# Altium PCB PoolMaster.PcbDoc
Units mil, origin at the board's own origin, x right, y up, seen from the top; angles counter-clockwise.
Board outline 5590 x 3205 mil, 2 copper layers (Top Layer, Bottom Layer); 45 components, 63 nets, 226 pads, 62 vias.
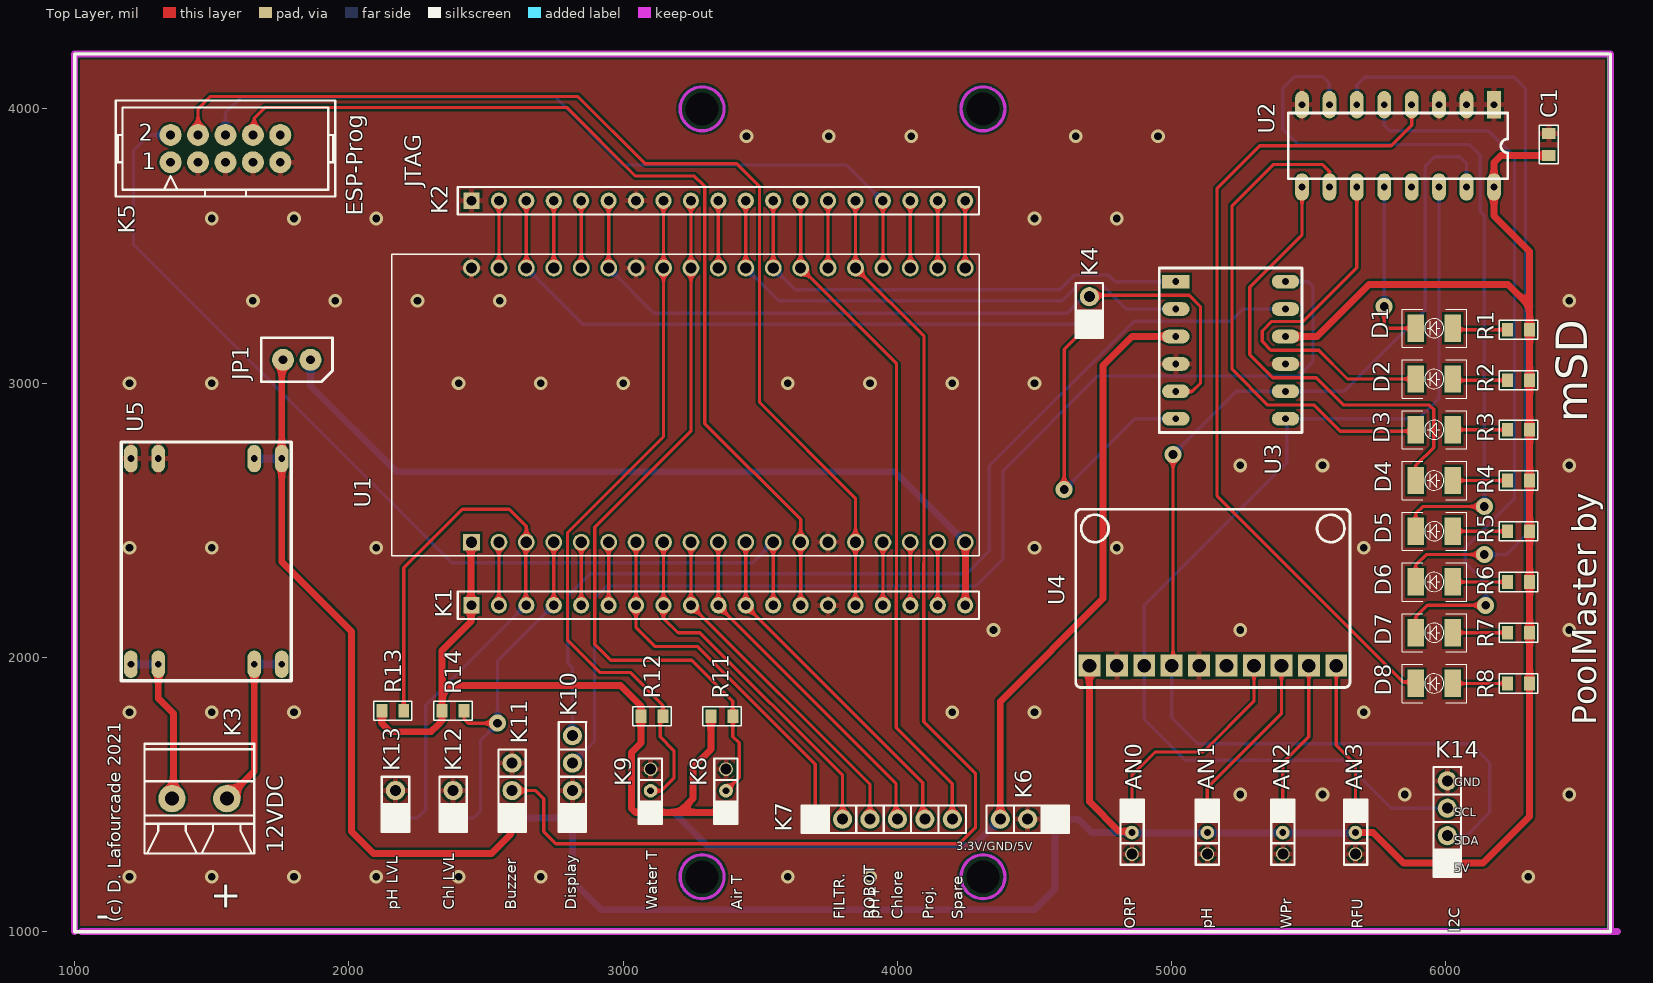
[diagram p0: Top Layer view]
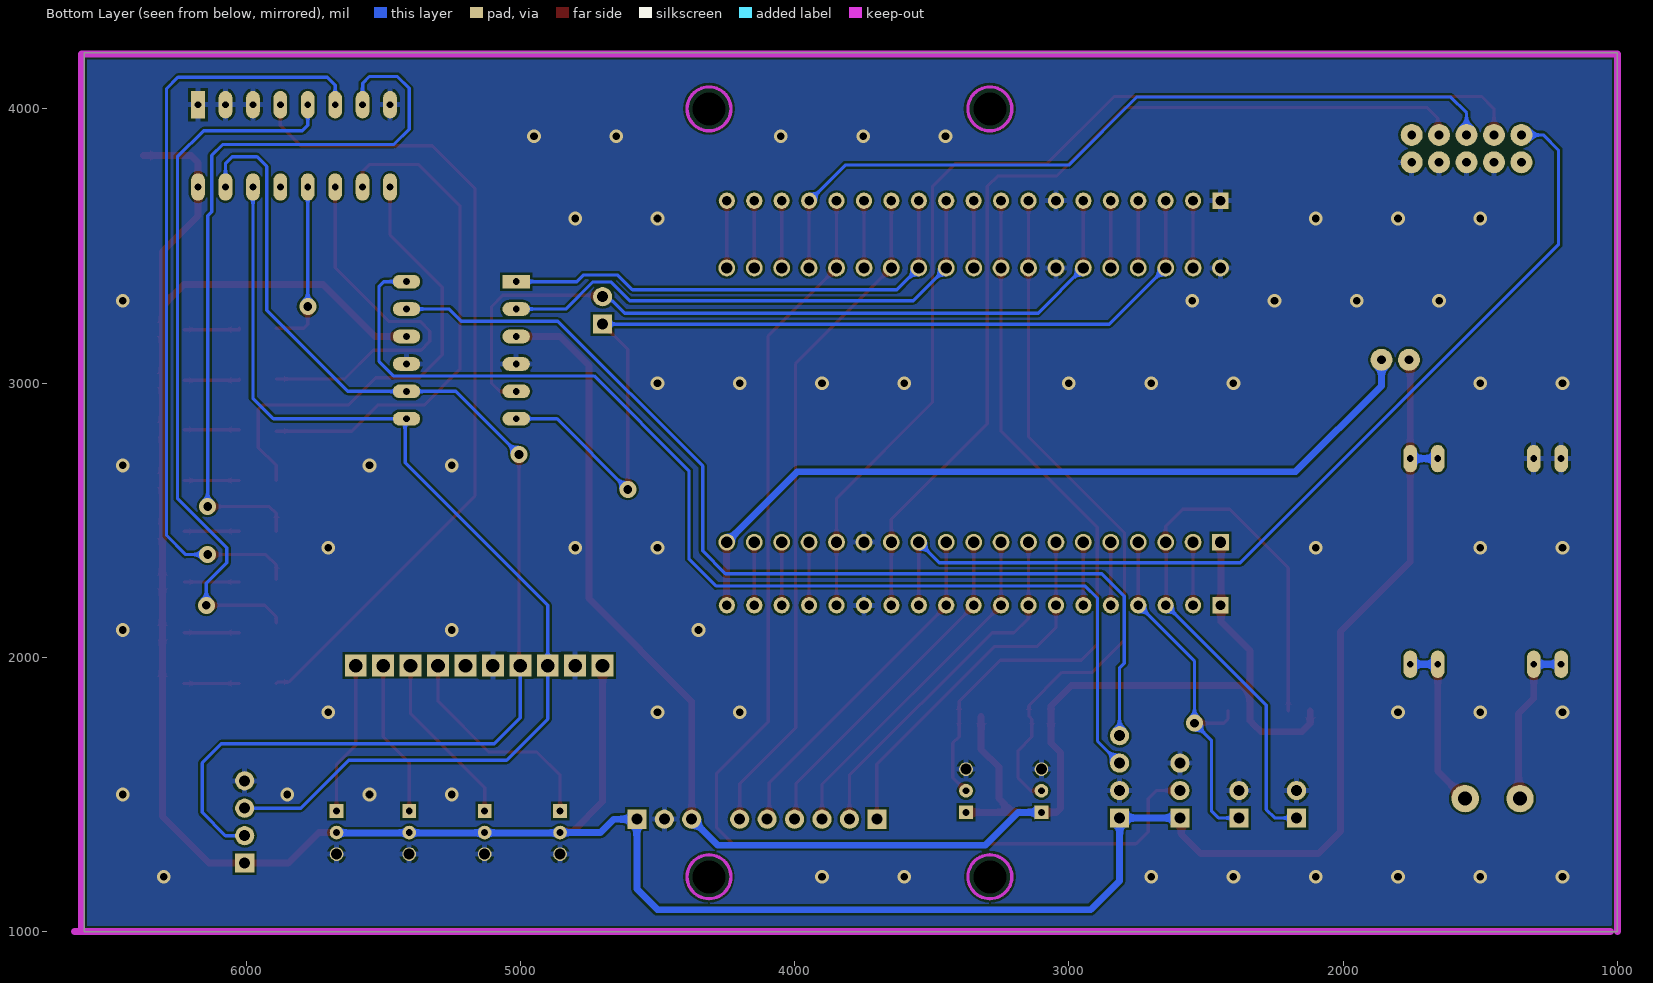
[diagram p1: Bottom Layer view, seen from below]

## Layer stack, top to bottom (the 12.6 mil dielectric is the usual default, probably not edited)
Top Solder: solder mask 0.4, Solder Resist, Dk 3.5
Top Layer: signal copper 1.4
Dielectric 1: dielectric 12.6, FR-4, Dk 4.8
Bottom Layer: signal copper 1.4
Bottom Solder: solder mask 0.4, Solder Resist, Dk 3.5

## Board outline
1000,1000 6590,1000 6590,4205 1000,4205

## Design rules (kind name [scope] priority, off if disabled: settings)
BoardOutlineClearance [All] p1: gap=7.87 ignorepadtopadclearanceinfootprint=FALSE except(15.75: Arc-SplitBarrior Arc-SplitContinuation Track-SplitBarrior Track-SplitContinuation SMDPad-SplitBarrior SMDPad-SplitContinuation THPad-SplitBarrior THPad-SplitContinuation Via-SplitBarrior Via-SplitContinuation Fill-SplitBarrior Fill-SplitContinuation Poly-SplitBarrior Poly-SplitContinuation Region-SplitBarrior Region-SplitContinuation Text-SplitBarrior Text-SplitContinuation)
Clearance "Clearance Bottom Layer" [OnLayer('Bottom Layer')] p1: gap=8 ignorepadtopadclearanceinfootprint=TRUE except(10: Arc-Text Track-Text SMDPad-Text THPad-Text Via-Text Fill-Text Poly-Text Region-Text Text-Text)
Clearance "Clearance Top Layer" [OnLayer('Top Layer')] p2: gap=8 ignorepadtopadclearanceinfootprint=TRUE except(10: Arc-Text Track-Text SMDPad-Text THPad-Text Via-Text Fill-Text Poly-Text Region-Text Text-Text)
Clearance [All] p3: gap=7.87 ignorepadtopadclearanceinfootprint=FALSE except(3.5: Arc-Arc Arc-Track Arc-SMDPad Track-Track Track-SMDPad SMDPad-SMDPad; 5: Arc-Via Track-Via SMDPad-Via THPad-Via Via-Via; 10: Arc-Text Track-Text SMDPad-Text THPad-Text Via-Text Fill-Text Poly-Text Region-Text Text-Text)
HoleSize [All] p1: absolutevalues=TRUE maxlimit=248.03 minlimit=7.87 maxpercent=80.000 minpercent=20.000
MinimumAnnularRing [All] p1: minimumring=3
MinimumSolderMaskSliver [All] p1: minsoldermaskwidth=3.94
PolygonConnect PolygonConnect_1 [All] p1: thpad.connectstyle=Relief thpad.reliefconductorwidth=20 thpad.reliefentries=4 thpad.polygonreliefangle="90 Angle" thpad.airgapwidth=10 smdpad.connectstyle=Relief smdpad.reliefconductorwidth=20 smdpad.reliefentries=4 smdpad.polygonreliefangle="90 Angle" smdpad.airgapwidth=10 via.connectstyle=Direct via.reliefconductorwidth=20 via.reliefentries=4 via.polygonreliefangle="90 Angle" via.airgapwidth=10
RoutingCorners [All] p1: cornerstyle=Round minsetback=100 maxsetback=100
RoutingVias [All] p1: holewidth=19.68 width=39.37 viastyle="Through Hole" minholewidth=7.87 minwidth=17.72 maxholewidth=39.37 maxwidth=78.74
SilkToSilkClearance [All] p1: silktosilkclearance=3.94
SilkToSolderMaskClearance [IsPad] p1: minsilkscreentomaskgap=3.94 clearancetoexposedcopper=TRUE
SolderMaskExpansion [All] p1: expansion=4 istentingtop=FALSE
Width [All] p1: maxlimit=100 minlimit=3.5 preferedwidth=15
25 further rules are at their usual default settings.

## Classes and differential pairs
net class Power: 3V3 5V GND NetJP1_1 NetK3_1 NetK3_2

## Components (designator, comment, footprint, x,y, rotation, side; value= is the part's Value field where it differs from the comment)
AN0 "HEADER 3" JST-1X3 4855,1440 r0 top
AN1 "HEADER 3" JST-1X3 5130,1440 r0 top
AN2 "HEADER 3" JST-1X3 5405,1440 r0 top
AN3 "HEADER 3" JST-1X3 5670,1440 r0 top
C1 "100n" 0805C-GENERIC 6375,3840 r90 top
D1 "Red" TOPLED-RED 6025,3200 r180 top
D2 "Red" TOPLED-RED 6025,3015 r180 top
D3 "Red" TOPLED-RED 6025,2830 r180 top
D4 "Red" TOPLED-RED 6025,2645 r180 top
D5 "Green" TOPLED-GREEN 6025,2460 r180 top
D6 "Green" TOPLED-GREEN 6025,2275 r180 top
D7 "Yellow" TOPLED-YELLOW 6025,2090 r180 top
D8 "Blue" TOPLED-BLUE 6025,1905 r180 top
JP1 "U/L" 2_PADS 1860,3085 r180 top
K1 "Header 19" HDR1X19 2447,2190 r0 top
K2 "Header 19" HDR1X19 2447,3665 r0 top
K3 "12VDC" MKDS15_2RMI 1555,1485 r180 top
K4 "I2C" HEADER-1X2 4700,3215 r180 top
K5 "ESP-Prog" HE10_10 1350,3805 r0 top
K6 "HEADER 3" HEADER-1X3 4575,1410 r270 top
K7 "HEADER 6" HEADER-1X6 3700,1410 r90 top
K8 "Air T" JST-1X3 3375,1435 r180 top
K9 "Water T" JST-1X3 3100,1435 r180 top
K10 "Display" HEADER-1X4 2815,1414.48 r180 top
K11 "Buzzer" HEADER-1X3 2595,1414.48 r180 top
K12 "Chl LVL" HEADER-1X2 2380,1414.48 r180 top
K13 "pH LVL" HEADER-1X2 2170,1414.48 r180 top
K14 "I2C-5V" HEADER-1X4 6005,1250 r180 top
R1 "3k3" 0805R-3K3 6295,3195 r180 top
R2 "3k3" 0805R-3K3 6295,3010 r180 top
R3 "3k3" 0805R-3K3 6295,2830 r180 top
R4 "3k3" 0805R-3K3 6295,2645 r180 top
R5 "3k3" 0805R-3K3 6295,2460 r180 top
R6 "3k3" 0805R-3K3 6295,2275 r180 top
R7 "3k3" 0805R-3K3 6295,2090 r180 top
R8 "3k3" 0805R-3K3 6295,1905 r180 top
R11 "10k" 0805R-10K 3320,1785 r0 top
R12 "10k" 0805R-10K 3065,1785 r0 top
R13 "10k" 0805R-10K 2120,1805 r0 top
R14 "10k" 0805R-10K 2340,1805 r0 top
U1 "ESP32-DEVKITC-32E" MODULE_ESP32-DEVKITC-32D 3225,2920 r90 top
U2 "PCF8574AN" DIP16 6175,4015 r270 top
U3 "SHIFTER 4CH" "SHIFTER 4CH" 5015,3370 r0 top
U4 "ADS1115" "ADS1115 Module" 5150,1970 r0 top
U5 "MP1584EN" MP1884EN 1205,1975 r90 top

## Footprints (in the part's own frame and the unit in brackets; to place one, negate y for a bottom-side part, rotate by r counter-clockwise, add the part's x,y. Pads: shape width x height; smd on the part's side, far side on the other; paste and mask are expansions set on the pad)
2_PADS [mil]
  round 80 hole 32: 1(0,0) 2(100,0)
  silkscreen extent -80,-80 180,80, body extent -50,-49 150,49, height 336
0805C-GENERIC [mil] "CAPACITOR 0805"
  rect 40x50 smd: 1(-10,0) 2(70,0)
  silkscreen extent -40,-35 100,35, body extent -11,-25 70,25, height 26
0805R-3K3 [mil] "RESISTOR 0805"
  rect 40x50 smd: 1(-10,0) 2(70,0)
  silkscreen extent -40,-35 100,35, body extent -11,-25 70,25, height 27
0805R-10K [mil] "RESISTOR 0805"
  rect 40x50 smd: 1(0,0) 2(80,0)
  silkscreen extent -30,-35 110,35, body extent -1,-25 80,25, height 27
"ADS1115 Module" [mil] "4 channels I2C ADC"
  rect 80x80 hole 50: 1(-450,0) 2(-350,0) 3(-250,0) 4(-150,0) 5(-50,0) 6(50,0) 7(150,0) 8(250,0) 9(350,0) 10(450,0)
  silkscreen extent -500,-80 500,570, body extent -550,-79 550,601, height 228
DIP16 [mil]
  rect 100x50 hole 25: 1(0,0)
  oval 100x50 hole 25: 2(0,-100) 3(0,-200) 4(0,-300) 5(0,-400) 6(0,-500) 7(0,-600) 8(0,-700) 9(300,-700) 10(300,-600) 11(300,-500) 12(300,-400) 13(300,-300) 14(300,-200) 15(300,-100) 16(300,0)
  silkscreen extent 30,-750 270,50, body extent -56,-751 357,52, height 317
HDR1X19 [mm] "Connector; Header; 19 Position"
  rect 1.5x1.5 hole 0.9: 1(0,0)
  round 1.5 hole 0.9: 2(2.54,0) 3(5.08,0) 4(7.62,0) 5(10.16,0) 6(12.7,0) 7(15.24,0) 8(17.78,0) 9(20.32,0) 10(22.86,0) 11(25.4,0) 12(27.94,0) 13(30.48,0) 14(33.02,0) 15(35.56,0) 16(38.1,0) 17(40.64,0) 18(43.18,0) 19(45.72,0)
  silkscreen extent -1.27,-1.27 46.99,1.27, body extent -1.4,-1.4 47.12,1.1, height 8.5
HE10_10 [mil]
  round 80 hole 32: 1(0,0) 2(0,100) 3(100,0) 4(100,100) 5(200,0) 6(200,100) 7(300,0) 8(300,100) 9(400,0) 10(400,100)
  silkscreen extent -200,-125 600,225, body extent -200,-135 600,225, height 354
HEADER-1X2 [mil]
  rect 70x70 hole 40: 1(0,0)
  round 70 hole 40: 2(0,-100)
  silkscreen extent -50,-150 50,50, body extent -50,-150 50,50, height 470
HEADER-1X3 [mil]
  rect 70x70 hole 40: 1(0,0)
  round 70 hole 40: 2(0,-100) 3(0,-200)
  silkscreen extent -50,-250 50,50, body extent -50,-250 50,50, height 470
HEADER-1X4 [mil]
  rect 70x70 hole 40: 1(0,0)
  round 70 hole 40: 2(0,-100) 3(0,-200) 4(0,-300)
  silkscreen extent -51,-350 50,50, body extent -50,-350 50,50, height 470
HEADER-1X6 [mil]
  rect 70x70 hole 40: 1(0,0)
  round 70 hole 40: 2(0,-100) 3(0,-200) 4(0,-300) 5(0,-400) 6(0,-500)
  silkscreen extent -50,-550 50,50, body extent -50,-550 50,50, height 470
JST-1X3 [mm] "JST 3 M"
  rect 1.27x1.27 hole 0.635: 1(0,0)
  round 1.27 hole 0.635: 2(0,-2)
  round 1.27 hole 1.016: 3(0,-4)
  silkscreen extent -1.07,-4.98 1.12,1.07, body extent -2.89,-6.01 1.61,1.89, height 6
MKDS15_2RMI [mm]
  round 2.54 hole 1.3: 1(0,0) 2(5.08,0)
  silkscreen extent -2.54,-5.08 7.62,5.08, body extent -2.87,-4.11 7.7,4.89, height 11.54
MODULE_ESP32-DEVKITC-32D [mm]
  rect 1.56x1.56 hole 1.04: 1(-12.7,19.76)
  round 1.56 hole 1.04: 2(-12.7,17.22) 3(-12.7,14.68) 4(-12.7,12.14) 5(-12.7,9.6) 6(-12.7,7.06) 7(-12.7,4.52) 8(-12.7,1.98) 9(-12.7,-0.56) 10(-12.7,-3.1) 11(-12.7,-5.64) 12(-12.7,-8.18) 13(-12.7,-10.72) 14(-12.7,-13.26) 15(-12.7,-15.8) 16(-12.7,-18.34) 17(-12.7,-20.88) 18(-12.7,-23.42) 19(-12.7,-25.96) 20(12.7,19.76) 21(12.7,17.22) 22(12.7,14.68) 23(12.7,12.14) 24(12.7,9.6) 25(12.7,7.06) 26(12.7,4.52) 27(12.7,1.98) 28(12.7,-0.56) 29(12.7,-3.1) 30(12.7,-5.64) 31(12.7,-8.18) 32(12.7,-10.72) 33(12.7,-13.26) 34(12.7,-15.8) 35(12.7,-18.34) 36(12.7,-20.88) 37(12.7,-23.42) 38(12.7,-25.96)
  silkscreen extent -13.95,-27.25 13.95,27.15, body extent -13.84,-31.3 14.1,24.28, height 7.14
MP1884EN [mil] "BoB MP1584EN DC-DC"
  oval 100x50 hole 25: 1(0,0) 2(0,-100) 3(0,-450) 4(0,-550) 5(750,-550) 6(750,-450) 7(750,-100) 8(750,0)
  silkscreen extent -60,-585 810,35, body extent -59,-610 807,60, height 268
"SHIFTER 4CH" [mil] "4 channels signal shifter"
  rect 100x50 hole 25: 1(0,0)
  oval 100x50 hole 25: 2(0,-100) 3(0,-200) 4(0,-300) 5(0,-400) 6(0,-500) 7(400,-500) 8(400,-400) 9(400,-300) 10(400,-200) 11(400,-100) 12(400,0)
  silkscreen extent -60,-550 460,50, body extent -100,-657 500,149, height 217
TOPLED-BLUE [mil]
  rect 60x100 smd: A(0,0) K(135,0)
  silkscreen extent -50,-70 185,70, body extent -20,-60 154,60, height 75
TOPLED-GREEN [mil]
  rect 60x100 smd: A(0,0) K(135,0)
  silkscreen extent -50,-70 185,70, body extent -20,-60 154,60, height 75
TOPLED-RED [mil]
  rect 60x100 smd: A(0,0) K(135,0)
  silkscreen extent -50,-70 185,70, body extent -20,-60 154,60, height 75
TOPLED-YELLOW [mil]
  rect 60x100 smd: A(0,0) K(135,0)
  silkscreen extent -50,-70 185,70, body extent -20,-60 154,60, height 75

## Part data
C1: library part CAP, "Capacitor"
D1 D2 D3 D4 D5 D6 D7 D8: library part LED
JP1: library part JUMPER, "Jumper"
K1 K2: "Header, 19-Pin"
K3 K4 K12 K13: library part "Header 2", "Header, 2-Pin"
K5: library part "Header 5X2", "Header, 5-Pin, Dual row"
K8 K9 K11: library part "Header 3", "Header, 3-Pin"
K10 K14: library part "Header 4", "Header, 4-Pin"
R1 R2 R3 R4 R5 R6 R7 R8 R11 R12 R13 R14: library part RES2, "Resistor"
U1: library part ESP32-DEVKITC-32D, "- Transceiver; 802.11 b/g/n _Wi-Fi, WiFi, WLAN_, BluetoothÂ® Smart Ready 4.x Dual Mode For Use With ESP-WROOM-32", Package=None
U2: "Remote 8-Bit I/O Expander for I2C-Bus, 2.5 to 6 V, -40 to 85 degC, 16-pin PDIP (N), Pb-Free (RoHS)", Manufacturer="Texas Instruments", Max Frequency(kHz)=100, Supplier Part Number 1=296-13106-5-ND, Voltage Nodes(V)="5, 3.3"

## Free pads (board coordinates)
  round 100 hole 120: 10(3288,4000) 11(4312,4000) 12(4312,1200)
  round 100 hole 120 unplated: 13(3288,1200)

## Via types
v1: diameter 50, hole 28, Top Layer to Bottom Layer, 55 vias
v2: diameter 62, hole 32, Top Layer to Bottom Layer, 7 vias

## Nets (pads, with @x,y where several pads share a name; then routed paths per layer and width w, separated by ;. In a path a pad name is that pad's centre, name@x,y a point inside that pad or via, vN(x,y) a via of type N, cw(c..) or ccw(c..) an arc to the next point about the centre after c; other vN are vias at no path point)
3V3: K1.1 K6.3 K8.1 K9.1 R11.1 R12.1 R13.1 R14.1 U1.1 U3.3 | length 6377.3
  Top Layer w25: R13.1 2120,1759 2150,1729 2300,1729 2325.25,1754.25 2340,1769 2340,1769.5 R14.1 2340,1837 2340,1867 ; U1.1 2445,2417.95 2445,2190 2445,2130 2340,2025 2340,1867 ; R11.1 3320,1665 3255,1600 3255,1485 3205,1435 ; K8.1 3205,1435 ; K6.3 4375,1840 4750,2215 4750,2980 4750,3064 4856,3170 U3.3 ; 2340,1867 2370,1897 2950,1897 2991,1897 3065,1823 R12.1 3065,1688 3030,1653 3030,1449.64 3044.64,1435 3205,1435
  Bottom Layer w25: K9.1 3185,1435 3305,1315 4280,1315 K6.3
5V: AN0.2 AN1.2 AN2.2 AN3.2 C1.1 JP1.2 K6.1 K10.1 K11.1 K14.1 R1.1 R2.1 R3.1 R4.1 R5.1 R6.1 R7.1 R8.1 U2.16 U3.10 U4.1 U5.5 U5.6 | length 11395.1
  Top Layer w25: JP1.2 1755,3080 U5.5 1755,2350 2010,2095 2010,1365 2090,1285 2520,1285 2590,1355 2590,1409.48 K11.1 ; U4.1@4700,1974.55 4700,1473.74 4807.7,1366.04 4850.22,1366.04 AN0.2 ; U3.10 5530,3170 5720,3360 6226,3360 6305,3281 ; AN3.2@5671.26,1360 AN3.2 5733.74,1361.26 5845,1250 K14.1 6135,1250 6305,1420 R8.1 R7.1 R5.1 R4.1 R2.1 R1.1 6305,3281 ; C1.1 6200,3830 6175,3805 6175,3610 6305,3480 6305,3281
  Bottom Layer w25: U5.6 U5.5 ; K11.1 K10.1 2815,1185 2920,1080 4500,1080 4575,1155 K6.1 4658.74,1410 4707.48,1361.26 AN0.2 4856.26,1360 5128.74,1360 AN1.2 5131.26,1360 5403.74,1360 AN2.2 5406.26,1360 5668.74,1360 AN3.2
GND: AN0.3 AN1.3 AN2.3 AN3.3 C1.2 K1.14 K2.1 K2.7 K5.3 K5.5 K5.7 K5.9 K6.2 K8.3 K9.3 K10.2 K11.3 K12.2 K13.2 K14.4 U1.14 U1.20 U1.26 U2.1 U2.2 U2.3 U2.8 U3.4 U3.9 U4.2 U4.5 U5.7 U5.8
  other v1: 1200,1200 1500,1200 1800,1200 2100,1200 2400,1200 2700,1200 3600,1200 3900,1200 6300,1200 5250,1500 5550,1500 5850,1500 6450,1500 1200,1800 1500,1800 1800,1800 4200,1800 4500,1800 5700,1800 4350,2100 5250,2100 6450,2100 1200,2400 1500,2400 2100,2400 4500,2400 4800,2400 5700,2400 5250,2700 5550,2700 6450,2700 1200,3000 1500,3000 2400,3000 2700,3000 3000,3000 3600,3000 3900,3000 4200,3000 4500,3000 1650,3300 1950,3300 2250,3300 2550,3300 6450,3300 1500,3600 1800,3600 2100,3600 4500,3600 4800,3600 3450,3900 3750,3900 4050,3900 4650,3900 4950,3900
NetAN0_1: AN0.1 U4.7 | length 816.8
  Top Layer w12: AN0.1 4855,1570 4940,1655 5115,1655 5300,1840 U4.7
NetAN1_1: AN1.1 U4.8 | length 641.8
  Top Layer w12: AN1.1 5130,1525 5400,1795 U4.8
NetAN2_1: AN2.1 U4.9 | length 569.4
  Top Layer w12: AN2.1 5405,1615 5500,1710 U4.9
NetAN3_1: AN3.1 U4.10 | length 559
  Top Layer w12: U4.10 5600,1680 5670,1610 AN3.1
NetD1_1: D1.A R1.2 | length 205
  Top Layer w12: D1.A 6025,3195 R1.2
NetD1_2: D1.K U2.12 | length 621.2
  Top Layer w12: v2(5775,3279) 5775,3215 5790.03,3199.97 5828,3199.97 ; 5828.03,3200 D1.K
  Bottom Layer w12: v2(5775,3279) U2.12
NetD2_1: D2.A R2.2 | length 205
  Top Layer w12: D2.A 6025,3010 R2.2
NetD2_2: D2.K U2.11 | length 1390
  Top Layer w12: U2.11 5675,3420 5480,3225 5365,3225 5330,3190 5330,3152.03 5362.03,3120 5536,3120 5641,3015 D2.K
NetD3_1: D3.A R3.2 | length 200
  Top Layer w12: D3.A R3.2
NetD3_2: D3.K U2.10 | length 1844.7
  Top Layer w12: U2.10 5575,3772 5550,3797 5370,3797 5220,3647 5220,3050 5350,2920 5520,2920 5615,2825 D3.K@5890,2825
NetD4_1: D4.A R4.2 | length 200
  Top Layer w12: D4.A R4.2
NetD4_2: D4.K U2.9 | length 1728.7
  Top Layer w12: U2.9 5475,3540 5285,3350 5285,3104 5369,3020 5527,3020 5627,2920 5939.46,2920 5955,2904.46 5955,2765 5890,2700 D4.K
NetD5_1: D5.A R5.2 | length 200
  Top Layer w12: D5.A R5.2
NetD5_2: D5.K U2.7 | length 2796.5
  Top Layer w12: D5.K 5890,2525 5915,2550 v2(6140,2550)
  Bottom Layer w12: U2.7 5575,4093 5550,4118 5448,4118 5405,4075 5405,3926 5461,3870 6085,3870 6125,3830 6125,3625 6140,3610 v2(6140,2550)
NetD6_1: D6.A R6.2 | length 200
  Top Layer w12: D6.A R6.2
NetD6_2: D6.K U2.6 | length 2840.3
  Top Layer w12: D6.K@5890,2285 5890,2337 5928,2375 v2(6140,2375)
  Bottom Layer w12: U2.6 5675,4086 5704,4115 6248.33,4115 6290,4073.33 6290,2445 6220,2375 v2(6140,2375)
NetD7_1: D7.A R7.2 | length 200.5
  Top Layer w12: D7.A R7.2@6225.47,2090
NetD7_2: D7.K U2.5 | length 2633.4
  Top Layer w12: D7.K@5890,2125 5890,2147.5 5932.5,2190 v2(6145,2190)
  Bottom Layer w12: U2.5 5775,3940 5795,3920 6155,3920 6250,3825 6250,2580 6070,2400 6070,2345 6145,2270 v2(6145,2190)
NetD8_1: D8.A R8.2 | length 203.3
  Top Layer w12: D8.A R8.2@6228.35,1905
NetD8_2: D8.K U2.4 | length 3008.4
  Top Layer w12: U2.4 5875,3940 5800,3865 5321,3865 5165,3709 5165,2590 5845,1910 5885,1910 D8.K
NetJP1_1: JP1.1 K1.19 U1.19 | length 2951.5
  Top Layer w25: K1.19@4245,2190 4248,2190 4248,2419.05 U1.19
  Bottom Layer w25: JP1.1 1860,2990 2173,2677 3990.05,2677 U1.19
NetK1_2: K1.2 U1.2 | length 230.8
  Top Layer w12: K1.2@2545,2190 2547.05,2192.05 U1.2
NetK1_3: K1.3 K13.1 R13.2 U1.3 | length 2390
  Top Layer w12: R13.2 2200,2326 2414,2540 2585,2540 2647.05,2477.95 U1.3 2645,2417.95 2645,2400 K1.3@2645,2190
  Bottom Layer w12: K13.1 2249.48,1414.48 2280,1445 2280,1825 K1.3@2645,2190
NetK1_4: K1.4 K12.1 R14.2 U1.4 | length 1359.4
  Top Layer w12: R14.2 2420,1775 2435,1760 v2(2542,1760) ; K1.4@2745,2190 2747.05,2192.05 U1.4
  Bottom Layer w12: K12.1 2454.48,1414.48 2480,1440 2480,1698 v2(2542,1760) 2542,1987 K1.4@2745,2190
NetK1_5: K1.5 U1.5 | length 230.8
  Top Layer w12: K1.5@2845,2190 2847.05,2192.05 U1.5
NetK1_6: K1.6 U1.6 | length 230.8
  Top Layer w12: K1.6@2945,2190 2947.05,2192.05 U1.6
NetK1_7: K1.7 K7.1 U1.7 | length 1371.3
  Top Layer w12: U1.7 K1.7 3047,2108 3115,2040 3270,2040 3700,1610 K7.1
NetK1_8: K1.8 K7.2 U1.8 | length 1327.4
  Top Layer w12: U1.8 K1.8 3147,2143 3200,2090 3280,2090 3800,1570 K7.2
NetK1_9: K1.9 K7.3 U1.9 | length 1280.5
  Top Layer w12: U1.9 K1.9 3900,1537 K7.3
NetK1_10: K1.10 K7.4 U1.10 | length 1282.2
  Top Layer w12: U1.10 3347.05,2192.05 3345,2190 3475,2060 3994.52,1540.48 3994.52,1415.48 K7.4
NetK1_11: K1.11 K7.5 U1.11 | length 1282.2
  Top Layer w12: U1.11 3447.05,2192.05 3445,2190 4092.02,1542.98 4092.02,1417.98 K7.5
NetK1_12: K1.12 K5.2 U1.12 | length 3577.2
  Top Layer w12: K1.12@3545,2190 3547.05,2192.05 U1.12
  Bottom Layer w12: K5.2 1270,3905 1215,3850 1215,3505 2375,2345 3472.05,2345 U1.12
NetK1_13: K1.13 K5.8 U1.13 | length 3513.5
  Top Layer w12: K5.8 1655,3910 1655,3965 1695,4005 1715,4005 2795,4005 3045,3755 3260,3755 3294.03,3720.97 3297.54,3717.46 3297.54,3424.52 3297.34,3424.31 3297.34,3415.69 3297.54,3415.48 3297.54,2852.46 3647.05,2502.95 U1.13 3647.05,2192.05 K1.13@3645,2190
NetK1_15: K1.15 K5.4 U1.15 | length 3969.9
  Top Layer w12: K5.4 1450,4000 1495,4045 2835,4045 3080,3800 3415,3800 3496.88,3718.12 3496.88,2931.12 3847.05,2580.95 U1.15 3847.05,2192.05 K1.15@3845,2190
NetK1_16: K1.16 U1.16 | length 230.8
  Top Layer w12: K1.16@3945,2190 3947.05,2192.05 U1.16
NetK1_17: K1.17 U1.17 | length 230.8
  Top Layer w12: K1.17@4045,2190 4047.05,2192.05 U1.17
NetK1_18: K1.18 U1.18 | length 230.8
  Top Layer w12: K1.18@4145,2190 4147.05,2192.05 U1.18
NetK2_2: K2.2 U1.21 | length 245.8
  Top Layer w12: K2.2@2545,3665 2547.05,3662.95 U1.21
NetK2_3: K2.3 K4.1 U1.22 U3.6 | length 3538.7
  Top Layer w12: K2.3@2645,3665 2647.05,3662.95 U1.22 ; v2(4608,2612) 4608,3123 K4.1
  Bottom Layer w12: U1.22 2852.05,3215 K4.1 ; v2(4608,2612) 4866,2870 U3.6
NetK2_4: K2.4 U1.23 | length 245.8
  Top Layer w12: K2.4@2745,3665 2747.05,3662.95 U1.23
NetK2_5: K2.5 U1.24 | length 245.8
  Top Layer w12: K2.5@2845,3665 2847.05,3662.95 U1.24
NetK2_6: K2.6 K4.2 U1.25 U3.5 | length 2897.5
  Top Layer w12: K2.6@2945,3665 2947.05,3662.95 U1.25 ; K4.2 4705,3320 4787.97,3320 5064,3320 5105,3279 5105,3000 5075,2970 U3.5
  Bottom Layer w12: U1.25 3112.05,3255 4620,3255 4664.52,3299.52 4668.83,3299.52 4684.31,3315 K4.2
NetK2_8: K2.8 K9.2 R12.2 U1.27 | length 2588.2
  Top Layer w12: K9.2 3138.74,1513.74 3185,1560 3185,1660 3135,1710 3135,1775 R12.2 3145,1825 3025,1945 2915,1945 2797.34,2062.66 2797.34,2455.34 3147.05,2805.05 U1.27 3147.05,3662.95 K2.8@3145,3665
NetK2_9: K2.9 K8.2 R11.2 U1.28 | length 2707.9
  Top Layer w12: K2.9@3245,3665 3247.05,3662.95 U1.28 3247.05,2825 2896.76,2474.71 2896.76,2048.24 2955,1990 3250,1990 3400,1840 R11.2 3400,1711 3423,1688 3423,1561.74 K8.2
NetK2_10: K2.10 U1.29 | length 245.8
  Top Layer w12: K2.10@3345,3665 3347.05,3662.95 U1.29
NetK2_11: K2.11 U1.30 U3.2 | length 1933.1
  Top Layer w12: K2.11@3445,3665 3447.05,3662.95 U1.30
  Bottom Layer w12: U1.30 3567.05,3300 4601,3300 4670,3369 4735,3369 4834,3270 U3.2
NetK2_12: K2.12 U1.31 U3.1 | length 1779.2
  Top Layer w12: K2.12@3545,3665 3547.05,3662.95 U1.31
  Bottom Layer w12: U1.31 3627.05,3340 4591,3340 4645,3394 4770,3394 4794,3370 U3.1
NetK2_13: K2.13 K7.6 U1.32 | length 2485.7
  Top Layer w12: K2.13@3645,3665 3647.05,3662.95 U1.32 3997,3070.05 3997,2254 3996,2253 3996,1744 4200,1540 K7.6
NetK2_14: K2.14 U1.33 | length 245.8
  Top Layer w12: K2.14@3745,3665 3747.05,3662.95 U1.33
NetK2_15: K2.15 K11.2 U1.34 | length 4333.8
  Top Layer w12: K11.2 2680.52,1514.48 2710,1485 2710,1365 2755,1320 4225,1320 4285,1380 4285,1576 4096,1765 4096,2345 4097,2346 4097,3170.05 U1.34 3847.05,3662.95 K2.15@3845,3665
NetK2_16: K2.16 K5.6 U1.35 | length 2901.9
  Top Layer w12: K2.16@3945,3665 3947.05,3662.95 U1.35
  Bottom Layer w12: K5.6 1550,3985 1608.5,4043.5 2751.5,4043.5 3000,3795 3815,3795 K2.16@3945,3665
NetK2_17: K2.17 U1.36 | length 245.8
  Top Layer w12: K2.17@4045,3665 4047.05,3662.95 U1.36
NetK2_18: K2.18 U1.37 | length 245.8
  Top Layer w12: K2.18@4145,3665 4147.05,3662.95 U1.37
NetK2_19: K2.19 U1.38 | length 245.8
  Top Layer w12: K2.19@4245,3665 4247.05,3662.95 U1.38
NetK3_1: K3.1 U5.3 U5.4 | length 631.4
  Top Layer w25: K3.1 1655,1585 U5.3
  Bottom Layer w25: U5.3 U5.4
NetK3_2: K3.2 U5.1 U5.2 | length 614.9
  Top Layer w25: U5.2 1305,1850 1360,1795 1360,1490 K3.2
  Bottom Layer w25: U5.1 U5.2
NetK10_3: K10.3 U3.12 | length 4180.3
  Bottom Layer w12: K10.3 2895.53,1695.01 2895.53,2215.53 2940,2260 4285,2260 4385,2360 4385,2680 4731,3026 5462.5,3026 5515,3078.5 5515,3352.97 5497.97,3370 U3.12
NetK10_4: K10.4 U3.11 | length 3747.4
  Bottom Layer w12: K10.4 2815,1961.87 2798.47,1978.4 2798.47,2223.47 2880,2305 4252,2305 4335,2388 4335,2698 4863,3226 5215,3226 5259,3270 U3.11
NetK14_2: K14.2 U2.15 U3.8 U4.4 | length 4482.9
  Top Layer w12: U4.4 5005,1975 v2(5005,2740)
  Bottom Layer w12: U4.4 5000,1780 5095,1685 6090,1685 6160,1615 6160,1435 6075,1350 K14.2 ; v2(5005,2740) 5235,2970 U3.8 5630,2970 5925,3265 5925,3790 5960,3825 6050,3825 6075,3800 U2.15
NetK14_3: K14.3 U2.14 U3.7 U4.3 | length 3913.1
  Bottom Layer w12: U2.14 5975,2945 5900,2870 U3.7 5420,2865 5420,2710 4900,2190 U4.3 4900,1775 5050,1625 5625,1625 5800,1450 K14.3
pads on no net: K5.1 K5.10 U2.13 U4.6

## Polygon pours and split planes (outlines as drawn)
GND on Top Layer "GND_L01_P000" (solid, pour order 0): 6600,4200 6600,1000 1000,1000 1000,4200
GND on Bottom Layer "GND_L02_P001" (solid, pour order 1): 1007.5,4200 6590,4200 6600,4210 6605,4205 6605,1000 1010,1000 1000,1010 1000,4205

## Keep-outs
Keep-Out Layer:
  circle w12: c4312,1200 r80
  circle w12: c3288,1200 r80
  circle w12: c4312,4000 r80
  circle w12: c3288,4000 r80
  lines w12: 1005,4200 1010,4200
  lines w25: 1000,1000 1000,4200 6600,4200 6600,1000 ; 1025,1000 6625,1000

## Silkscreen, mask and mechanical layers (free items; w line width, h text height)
Top Overlay:
  lines w12: 1000,1000 1000,4200 6600,4200 6600,1000 1000,1000
  text "JTAG" at 2263.04,3715.04 h60 r90
  text "mSD" at 6552.88,2857.4 h196.85 r90
  text "PoolMaster by" at 6577.24,1751.77 h150 r90
  text "GND" at 6029.37,1530.96 h30 r359.67
  text "SCL" at 6029.37,1420.96 h30 r359.67
  text "SDA" at 6029.37,1315.96 h30 r359.67
  text "3.3V/GND/5V" at 4214.37,1295.96 h30 r359.67
  text "5V" at 6029.37,1215.96 h30 r359.67
  text "+" at 1494.4,1086.96 h100
  text "FILTR." at 3807.88,1045 h40 r90
  text "ROBOT" at 3917.88,1045 h40 r90
  text "pH+" at 3935,1045 h40 r90
  text "Chlore" at 4019.04,1045 h40 r90
  text "Proj." at 4132.37,1045 h40 r90
  text "Spare" at 4237.37,1045 h40 r90
  text "(c) D. Lafourcade 2021" at 1185,1035 h80 r90
  text "-" at 1077.62,1014.16 h100
  text "ORP" at 4867.37,1010 h40 r90
  text "pH" at 5147.37,1010 h40 r90
  text "WPr" at 5437.37,1010 h40 r90
  text "RFU" at 5697.37,1010 h40 r90
  text "I2C" at 6051.09,997.89 h40 r90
